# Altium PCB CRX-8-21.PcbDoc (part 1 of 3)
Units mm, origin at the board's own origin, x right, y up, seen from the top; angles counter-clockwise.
Board outline 160.02 x 101.6 mm, 2 copper layers (TopLayer, BottomLayer), stack 1.535 mm thick; 254 components, 127 nets, 595 pads, 4322 vias.
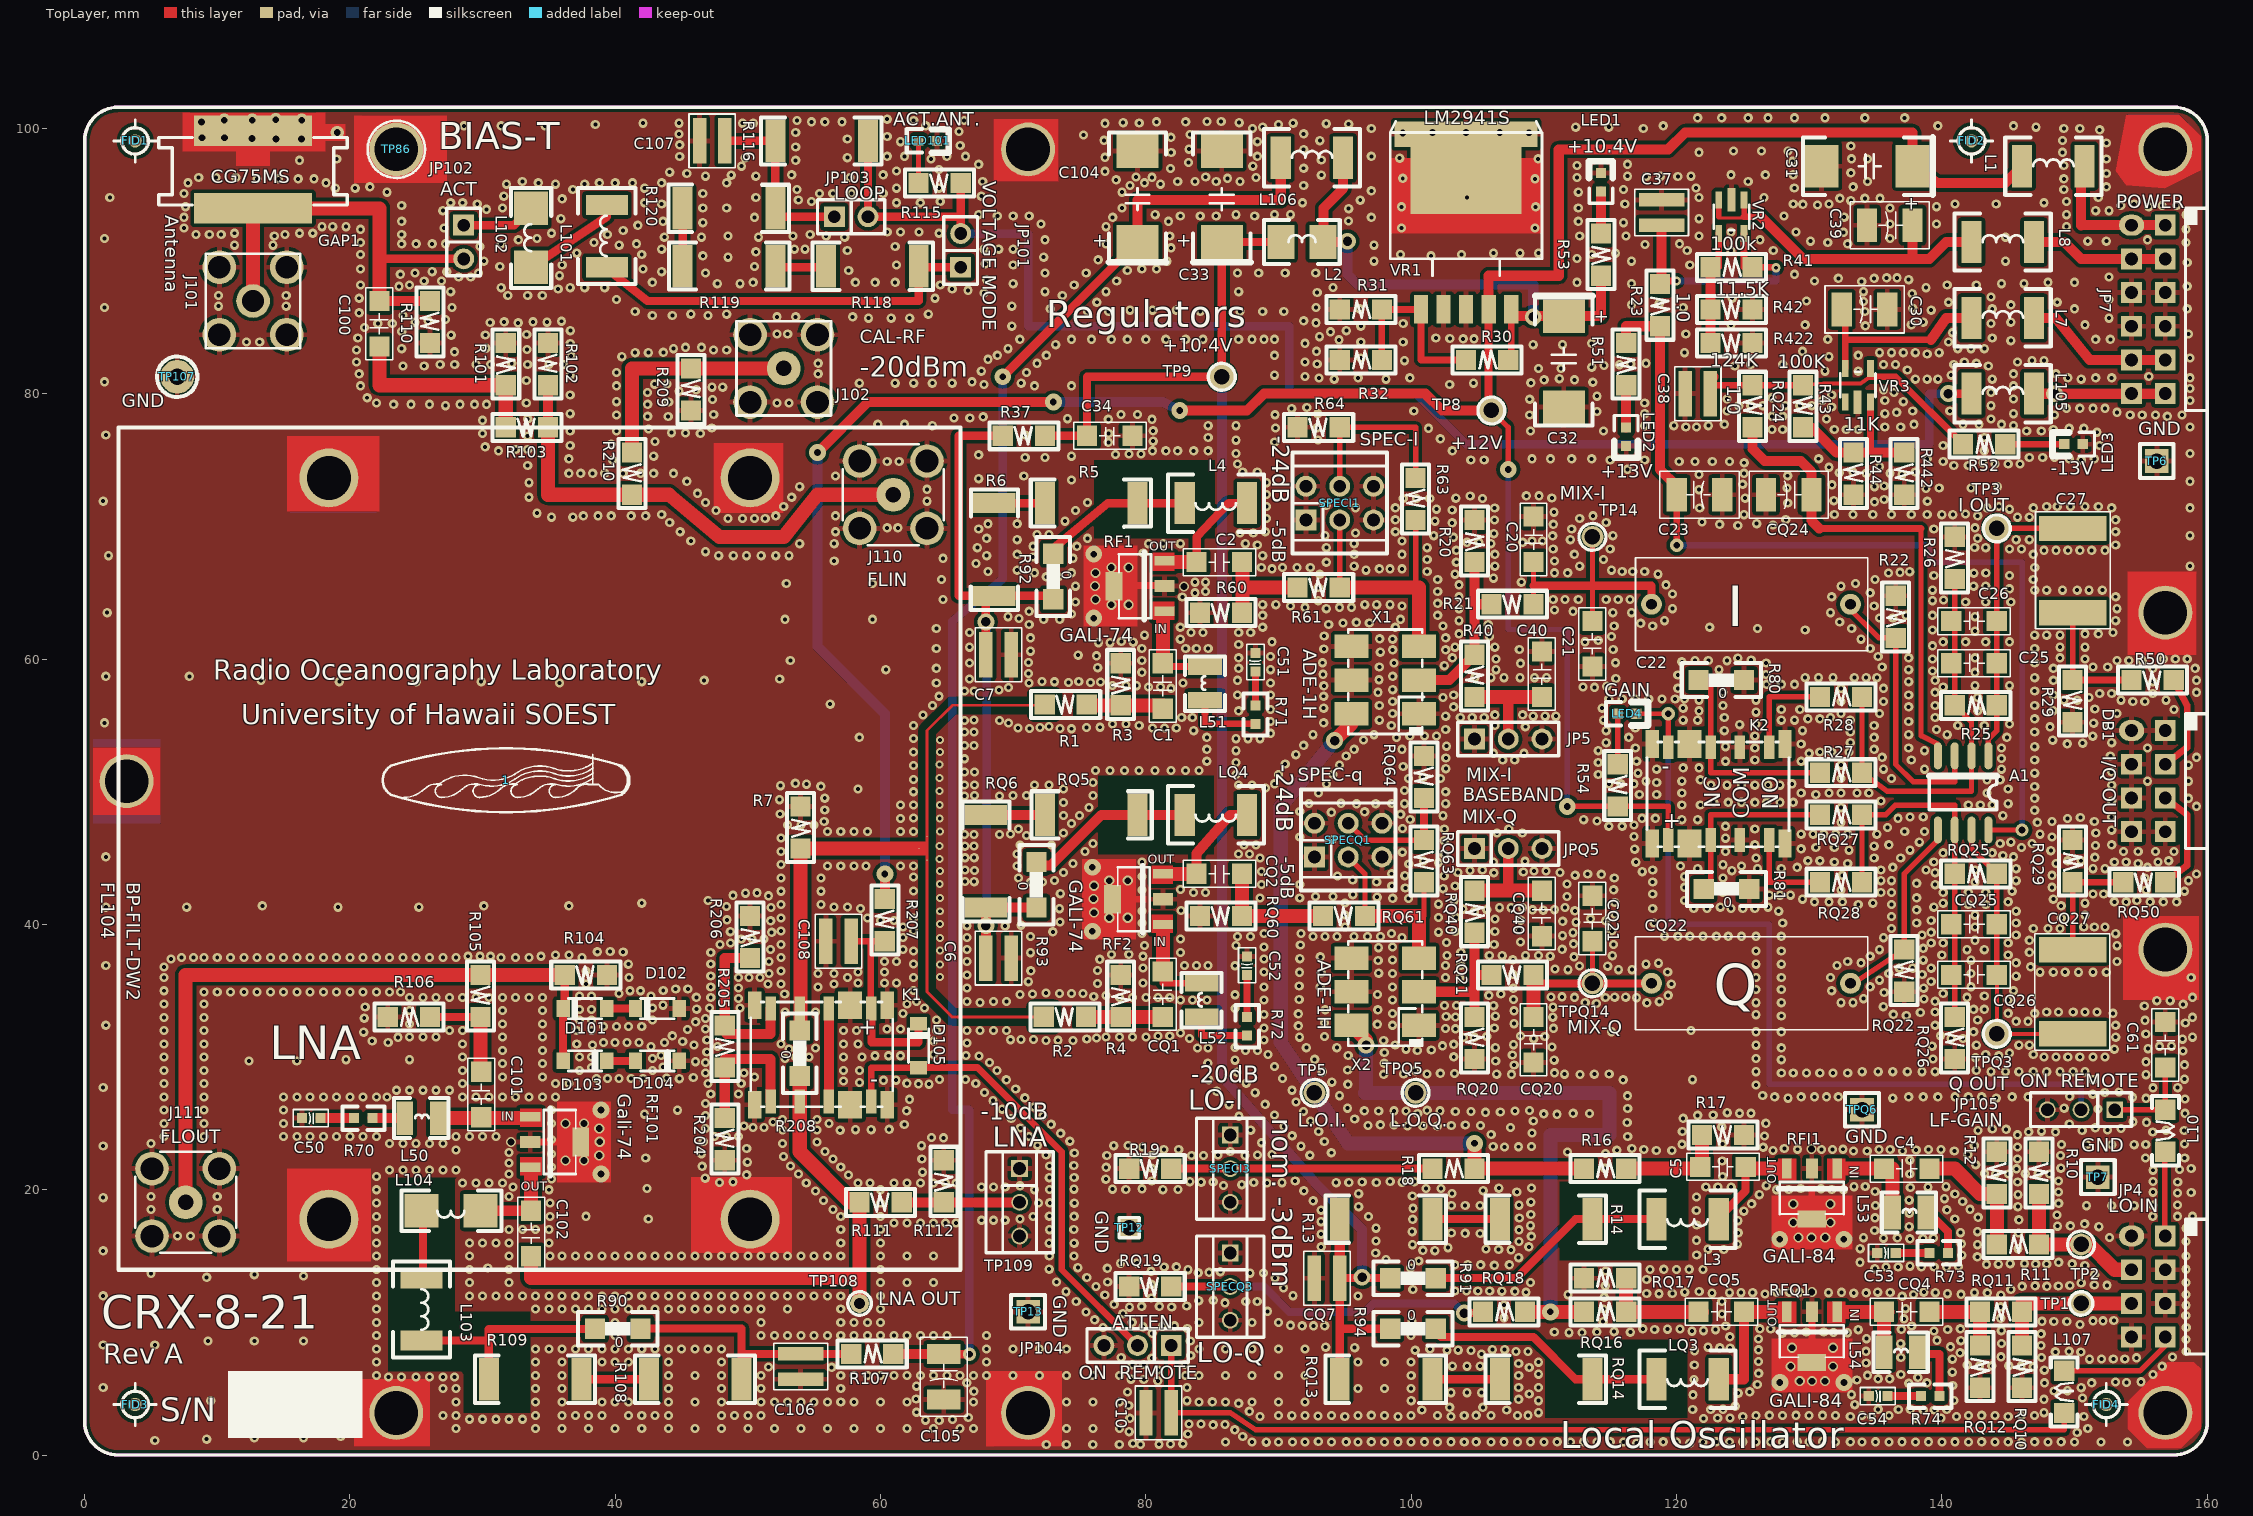
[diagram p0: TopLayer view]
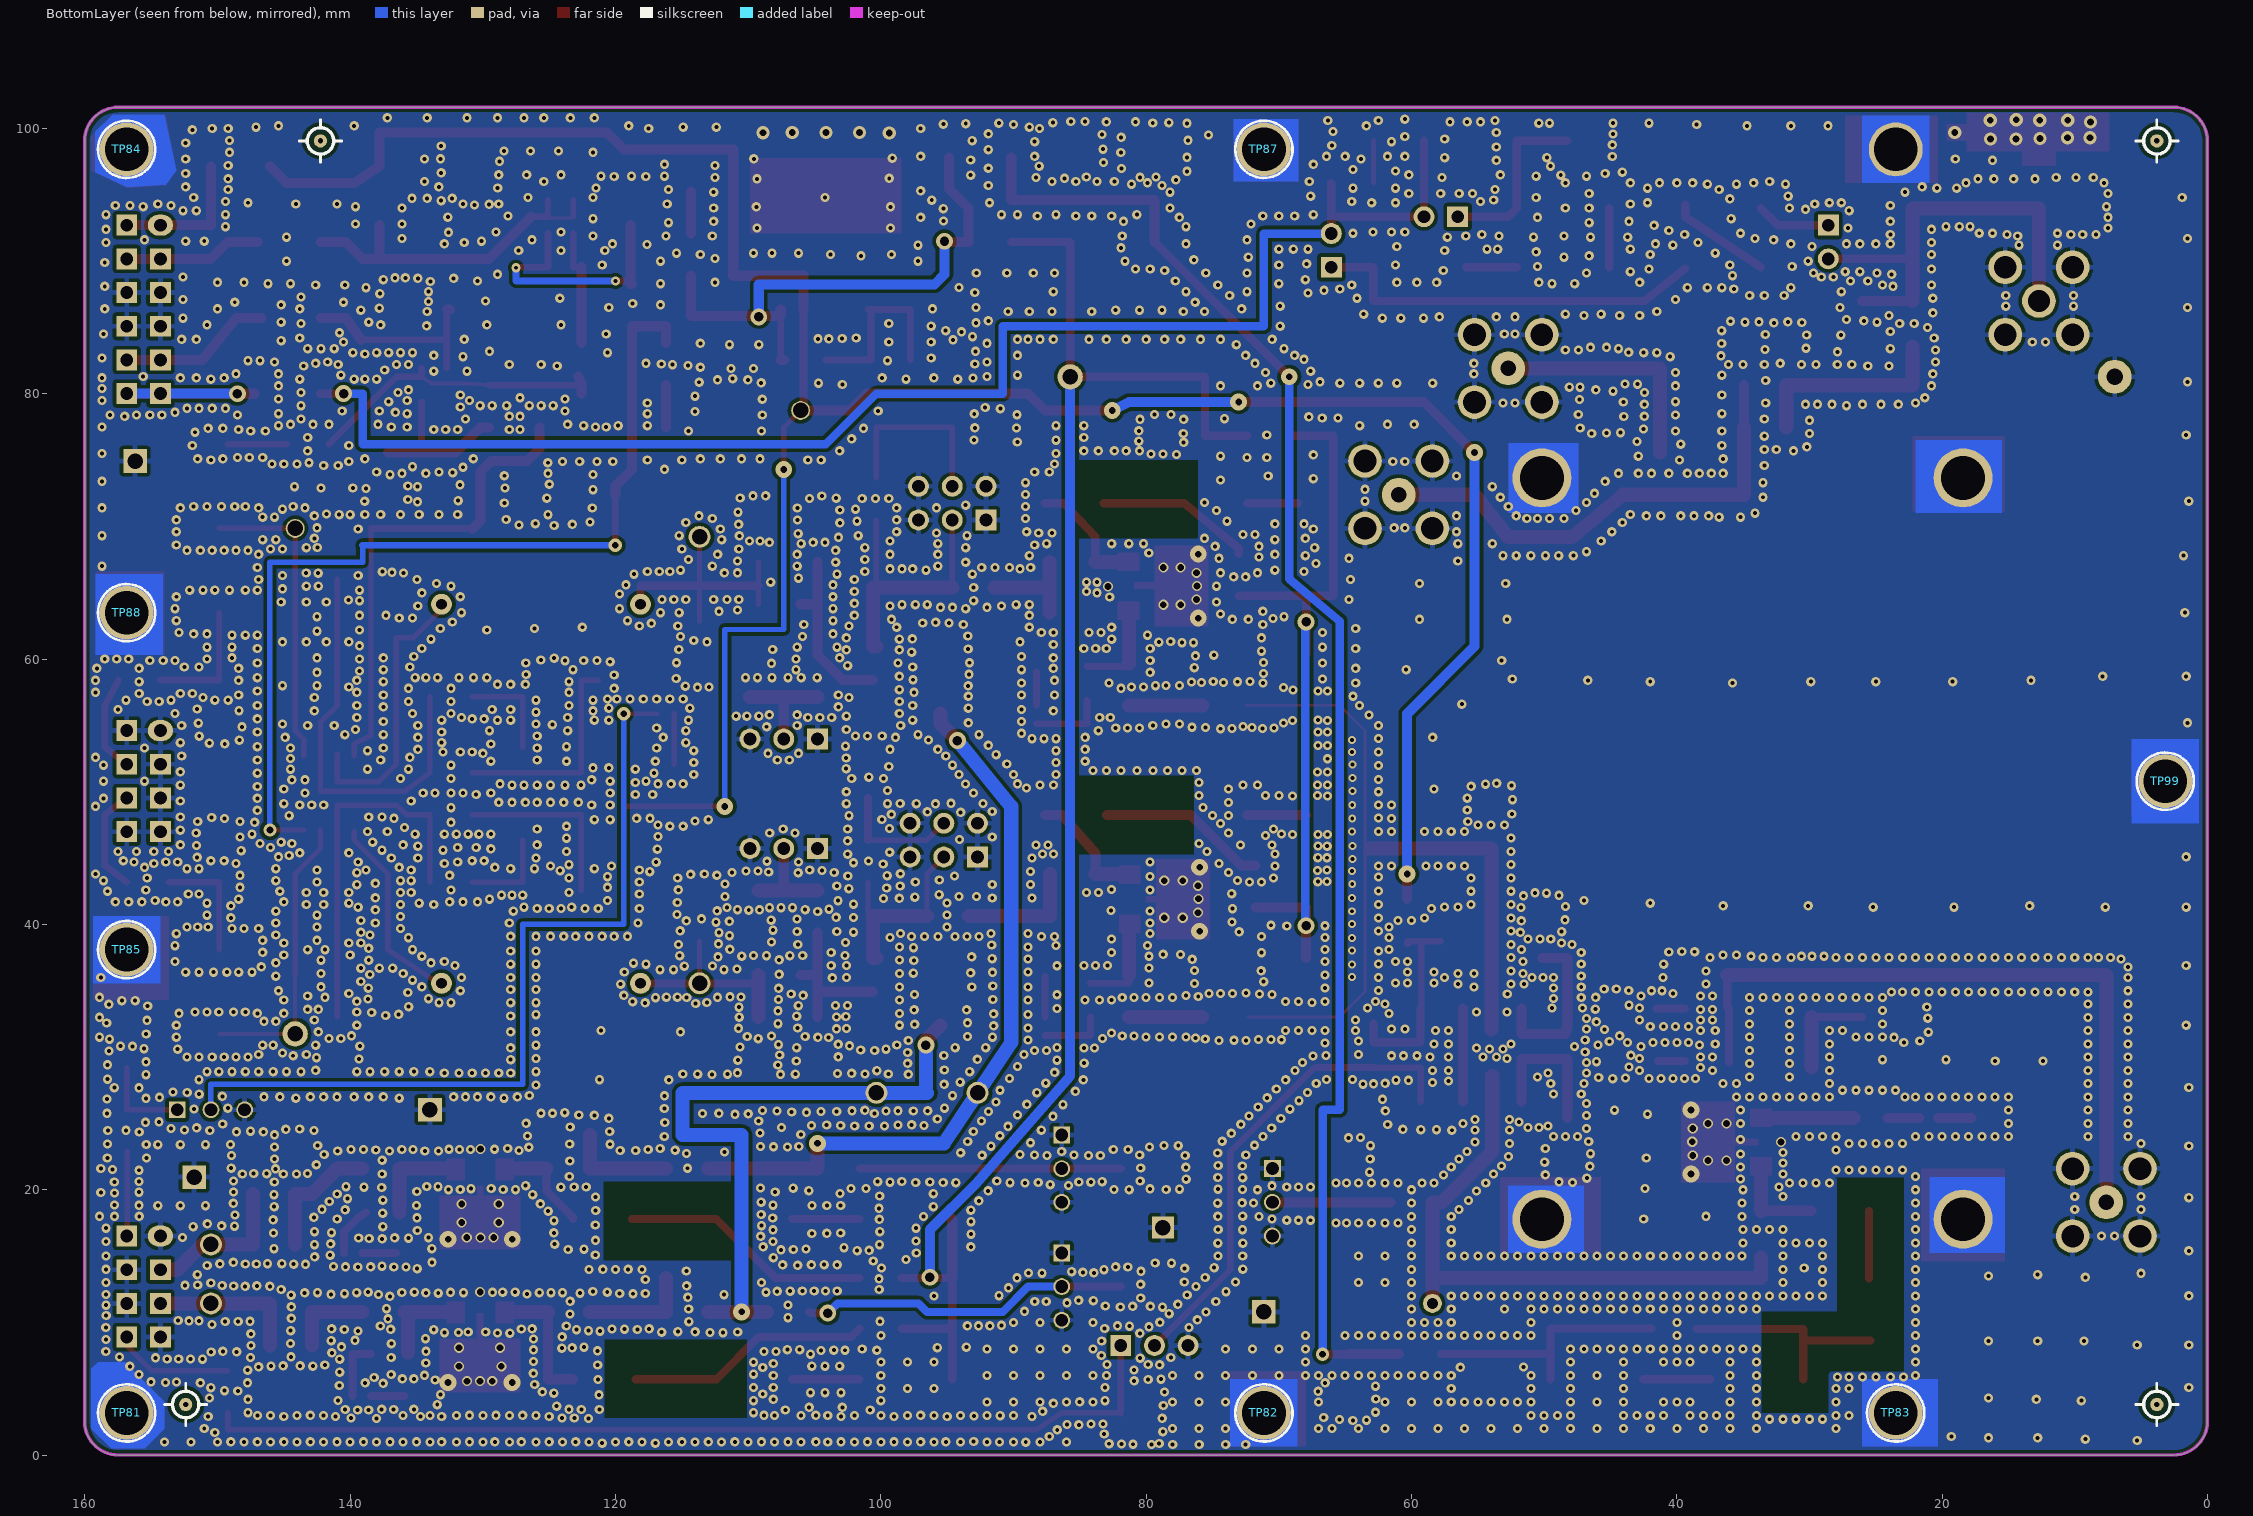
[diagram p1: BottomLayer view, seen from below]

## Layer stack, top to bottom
TopSolder: solder mask 0.02, Solder Resist, Dk 4
TopLayer: signal copper 0.035
Dielectric1: dielectric 1.465, FR-4, Dk 4.74
BottomLayer: signal copper 0.035
BottomSolder: solder mask 0.02, Solder Resist, Dk 4

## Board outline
0,2.54 0,99.06 cw(c2.54,99.06) 2.54,101.6 157.48,101.6 cw(c157.48,99.06) 160.02,99.06 160.02,2.54 cw(c157.48,2.54) 157.48,0 2.54,0 cw(c2.54,2.54)

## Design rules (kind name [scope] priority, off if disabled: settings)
Clearance Clearance_4 [InNet('RF') vs InPolygon] p1: gap=0.55 ignorepadtopadclearanceinfootprint=FALSE
Clearance Clearance_2 [InNet('RF') vs InPolygon] p2: gap=0.55 ignorepadtopadclearanceinfootprint=FALSE
Clearance Clearance_3 [InNet('RF') vs InPolygon] p3: gap=0.55 ignorepadtopadclearanceinfootprint=FALSE
Clearance Clearance_1 [InPolygon] p4: gap=0.257 ignorepadtopadclearanceinfootprint=FALSE
Clearance [InNet('rfi2x') vs InPolygon] p5: gap=0.55 ignorepadtopadclearanceinfootprint=FALSE
ComponentClearance [All] p1 off: gap=0.254 collisioncheckmode=3 verticalgap=0.254 showdistances=FALSE
FabricationTestPointUsage TestPointUsage [All] p1: valid=0 allowmultiple=FALSE
FabricationTestpoint Testpoint [All] p1: side=3 testpointundercomponent=TRUE minsize=1.016 maxsize=2.54 preferedsize=1.524 minholesize=0.508 maxholesize=1.016 preferedholesize=0.813 testpointgrid=0.025 allowsidetop=TRUE allowsidebottom=TRUE usegrid=TRUE gridtolerance=0
HoleSize [All] p1: absolutevalues=TRUE maxlimit=10 minlimit=0.025 maxpercent=80.000 minpercent=20.000
PlaneClearance PlaneClearance_15 [HasPad('TP88-TP')] p1 off: clearance=1.27
PlaneClearance PlaneClearance_16 [HasPad('TP85-TP')] p2 off: clearance=1.27
PlaneClearance PlaneClearance_13 [HasPad('TP86-TP')] p3 off: clearance=1.27
PlaneClearance PlaneClearance_14 [HasPad('TP84-TP')] p4 off: clearance=1.27
PlaneClearance PlaneClearance_17 [HasPad('TP81-TP')] p5 off: clearance=1.27
PlaneClearance PlaneClearance_20 [HasPad('TP99-TP')] p6 off: clearance=1.27
PlaneClearance PlaneClearance_21 [HasPad('TP83-TP')] p7 off: clearance=1.27
PlaneClearance PlaneClearance_18 [HasPad('TP87-TP')] p8 off: clearance=1.27
PlaneClearance PlaneClearance_19 [HasPad('TP82-TP')] p9 off: clearance=1.27
PlaneClearance PlaneClearance_4 [HasPad('TPQ3-TP')] p10 off: clearance=0.381
PlaneClearance PlaneClearance_5 [HasPad('TP8-TP')] p11 off: clearance=0.381
PlaneClearance PlaneClearance_6 [HasPad('TP14-TP')] p12 off: clearance=0.381
PlaneClearance PlaneClearance_1 [HasPad('TP3-TP')] p13 off: clearance=0.381
PlaneClearance PlaneClearance_2 [HasPad('TP2-TP')] p14 off: clearance=0.381
PlaneClearance PlaneClearance_3 [HasPad('TP1-TP')] p15 off: clearance=0.381
PlaneClearance PlaneClearance_10 [HasPad('TP5-TP')] p16 off: clearance=0.381
PlaneClearance PlaneClearance_11 [HasPad('TP12-TP')] p17 off: clearance=0.381
PlaneClearance PlaneClearance_12 [HasPad('TP108-TP')] p18 off: clearance=0.381
PlaneClearance PlaneClearance_7 [HasPad('TPQ14-TP')] p19 off: clearance=0.381
PlaneClearance PlaneClearance_8 [HasPad('TP9-TP')] p20 off: clearance=0.381
PlaneClearance PlaneClearance_9 [HasPad('TPQ5-TP')] p21 off: clearance=0.381
PlaneClearance [All] p22 off: clearance=0.254
PlaneConnect PlaneConnect_1 [All] p1 off: planeconnectstyle=Relief reliefexpansion=0.508 reliefentries=4 reliefconductorwidth=0.254 reliefairgap=0.254
PlaneConnect [All] p2 off: planeconnectstyle=Relief reliefexpansion=0.508 reliefentries=4 reliefconductorwidth=0.254 reliefairgap=0.254
PolygonConnect PolygonConnect_1 [IsVia] p1 off: connectstyle=Direct reliefconductorwidth=0.254 reliefentries=4 polygonreliefangle="90 Angle" airgapwidth=0.254
PolygonConnect PolygonConnect_2 [All] p2: thpad.connectstyle=Relief thpad.reliefconductorwidth=0.4 thpad.reliefentries=4 thpad.polygonreliefangle="90 Angle" thpad.airgapwidth=0.257 smdpad.connectstyle=Relief smdpad.reliefconductorwidth=0.4 smdpad.reliefentries=4 smdpad.polygonreliefangle="90 Angle" smdpad.airgapwidth=0.257 via.connectstyle=Direct via.reliefconductorwidth=0.254 via.reliefentries=4 via.polygonreliefangle="90 Angle" via.airgapwidth=0.254
PolygonConnect [All] p3 off: connectstyle=Relief reliefconductorwidth=0.254 reliefentries=4 polygonreliefangle="90 Angle" airgapwidth=0.257
RoutingPriority [All] p1: routingpriority=2
RoutingVias [All] p1: holewidth=0.3 width=0.7 viastyle="Through Hole" minholewidth=0.3 minwidth=0.7 maxholewidth=1.1 maxwidth=2
SilkToSilkClearance [All] p1 off: silktosilkclearance=0.254
SilkToSolderMaskClearance [IsPad] p1 off: minsilkscreentomaskgap=0.254 clearancetoexposedcopper=TRUE
SolderMaskExpansion [All] p1: expansion=0.051
UnpouredPolygon [All] p1 off:
Width [All] p1: maxlimit=10 minlimit=0.2 preferedwidth=0.635 bottomlayer_minwidth=0.254 minimp=50.000000 maximp=50.000000 favimp=50.000000
20 further rules are at their usual default settings.

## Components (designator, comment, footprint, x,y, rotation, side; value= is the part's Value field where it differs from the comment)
1 "" LOGOTINY 31.773,50.867 r0 top
A1 "OPA2227UA" SO-8 143.51,52.705 r270 top
C1 "22nF" C1206 81.28,59.69 r270 top
C2 "22nF" C1206 83.82,67.31 r0 top
C4 "22nF" C1206 139.065,21.59 r180 top
C5 "470nF" C1206 121.793,21.717 r0 top
C6 "470nF" C0612 67.945,37.465 r0 top
C7 "470nF" C0612 67.945,60.325 r0 top
C10 "470nF" C0612 81.915,3.175 r180 top
C20 "1nF" C1206 109.22,67.31 r90 top
C21 "100nF  NPO" C1206 113.665,62.865 r270 top
C22 "470nF" BFC2_416#1 118.11,64.135 r0 top
C23 "4.7uF" C1210 120.015,72.39 r0 top
C25 "1800pF NPO" C1206 144.145,59.69 r180 top
C26 "3650" C1206 144.145,62.865 r180 top
C27 "22uF 25V NP" 2220 149.86,69.85 r270 top
C30 "4.7uF" C1210 135.89,86.36 r180 top
C31 "22uF 20V" C2917 137.795,97.155 r180 top
C32 "22uF 20V" C2917 111.506,85.852 r270 top
C33 "22uF 20V" C2917 85.725,91.44 r90 top
C34 "470nF" C1206 75.565,76.835 r0 top
C37 "470nF" C0612 118.872,92.71 r90 top
C38 "470nF" C0612 122.555,80.01 r180 top
C39 "4.7uF" C1210 137.795,92.71 r180 top
C40 "1nF" C1206 109.855,57.15 r90 top
C50 "330pF" C0603 17.78,25.4 r180 top
C51 "330pF" C0603 88.265,59.055 r90 top
C52 "330pF" C0603 87.63,36.195 r90 top
C53 "330pF" C0603 136.525,15.24 r180 top
C54 "330pF" C0603 135.89,4.445 r180 top
C61 "22nF" C1206 156.845,29.21 r90 top
C100 "22nF" C1206 22.225,86.995 r270 top
C101 "10nF" C1206 29.9,28.9 r270 top
C102 "47nF" C1206 33.655,18.415 r270 top
C104 "22uF 20V" C2917 79.375,91.44 r90 top
C105 "4.7uF" C1210 64.77,7.62 r270 top
C106 "470nF" C0612 53.975,7.62 r270 top
C107 "470nF" C0612 48.26,99.06 r180 top
C108 "470nF" C0612 57.785,38.735 r180 top
CQ1 "22nF" C1206 81.28,36.449 r270 top
CQ2 "22nF" C1206 83.82,43.815 r0 top
CQ4 "22nF" C1206 139.065,10.795 r180 top
CQ5 "470nF" C1206 125.095,10.795 r180 top
CQ7 "470nF" C0612 94.615,13.335 r180 top
CQ20 "1nF" C1206 109.22,33.02 r270 top
CQ21 "100nF  NPO" C1206 113.665,38.735 r90 top
CQ22 "470nF" BFC2_416#2 118.11,35.56 r0 top
CQ24 "4.7uF" C1210 130.175,72.39 r180 top
CQ25 "1800pF NPO" C1206 144.145,40.005 r180 top
CQ26 "FSV" C1206 144.145,36.195 r180 top
CQ27 "22uF 25V NP" 2220 149.86,31.75 r90 top
CQ40 "1nF" C1206 109.855,42.545 r270 top
D101 "1N4148W" SOD123 37.719,33.655 r180 top
D102 "1N4148W" SOD123 43.18,33.655 r180 top
D103 "1N4148W" SOD123 37.719,29.718 r0 top
D104 "1N4148W" SOD123 43.18,29.718 r0 top
D105 "1N4148W" SOD123 62.865,30.861 r90 top
DB1 "I/Q OUT" TSW-4X2M 154.305,54.61 r90 top locked
FID1 "" FIDUCIAL2 3.81,99.06 r0 top
FID2 "" FIDUCIAL2 142.24,99.06 r0 top
FID3 "" FIDUCIAL2 3.81,3.81 r0 top
FID4 "" FIDUCIAL2 152.4,3.81 r0 top
FL104 "BP-FILT-DW2" BP-FILT-DW2 34.29,45.72 r90 top locked
GAP1 "CG75MS" SG-1 12.7,93.98 r90 top
J101 "Antenna" MCX_SMA#1 12.7,86.995 r0 top
J102 "CAL-RF" MCX_SMA#2 52.705,81.915 r0 top
J110 "FLIN" MCX_SMA#2 60.96,72.39 r0 top
J111 "FLOUT" MCX_SMA#2 7.62,19.05 r0 top
JP4 "LO IN" TSW-4X2M 154.305,16.51 r90 top locked
JP5 "MIX-I" SIP3#1 104.775,53.975 r0 top
JP7 "POWER" TSW-6X2M 154.305,92.71 r90 top locked
JP101 "VOLTAGE MODE" SIP2 66.04,89.535 r90 top
JP102 "ACT" SIP2 28.575,92.71 r270 top
JP103 "LOOP" SIP2 56.515,93.345 r0 top
JP104 "ATTEN" SIP3#1 81.915,8.255 r180 top
JP105 "LF-GAIN" SIP3#2 153.035,26.035 r180 top
JPQ5 "MIX-Q" SIP3#1 104.775,45.72 r0 top
K1 "G6K-2F-RF-S DC12" RELAY-RF 59.309,33.655 r180 top
K2 "G6K-2F-RF-S DC12" RELAY-RF 119.38,46.355 r0 top
L1 "Ferrite" L1812 146.05,97.155 r0 top
L2 "2.2uH" L1210#1 90.17,91.44 r0 top
L3 "4.7uH" L1812 123.19,17.78 r180 top
L4 "4.7uH" L1812 87.63,71.755 r180 top
L7 "Ferrite" L1812 142.24,85.725 r0 top
L8 "Ferrite" L1812 142.24,91.44 r0 top
L10 "Ferrite" L1206 156.845,22.86 r90 top
L50 "620nH" L1008 24.13,25.4 r0 top
L51 "620nH" L1008 84.455,56.896 r90 top
L52 "620nH" L1008 84.201,33.02 r90 top
L53 "620nH" L1008 136.271,18.288 r0 top
L54 "620nH" L1008 135.636,7.747 r0 top
L101 "4.7uH" L1812 39.37,89.535 r90 top
L102 "0.47uH" L1210#2 33.655,89.535 r90 top
L103 "4.7uH" L1812 25.4,13.335 r270 top
L104 "0.47uH" L1210#2 29.845,18.415 r180 top
L105 "Ferrite" L1812 142.24,80.01 r0 top
L106 "Ferrite" L1812 90.17,97.79 r0 top
L107 "Ferrite" L1206 149.225,6.35 r270 top
LED1 "+10.4V" LED0603 114.3,95.25 r90 top
LED2 "+13V" LED0603 116.205,77.47 r270 top
LED3 "-13V" LED0603 150.622,76.2 r180 top
LED4 "GAIN" LED0603 115.57,55.88 r0 top
LED101 "ACT.ANT." LED0603 62.865,99.06 r0 top
LQ3 "4.7uH" L1812 123.19,5.715 r180 top
LQ4 "4.7uH" L1812 87.63,48.26 r180 top
R1 "75" R1206 72.371,56.588 r0 top
R2 "75" R1206 72.308,33.033 r0 top
R3 "49.9" R1206 78.105,56.515 r90 top
R4 "49.9" R1206 78.105,33.02 r90 top
R5 "27R4 1W" R2512 72.39,71.755 r0 top
R6 "27R4 1W" R2512 68.58,64.77 r90 top
R7 "499" R1206 53.975,45.72 r90 top
R10 "442" R1206 147.32,22.86 r270 top
R11 "11.8" R1206 147.32,15.875 r180 top
R12 "442" R1206 144.145,22.86 r270 top
R13 "20R5 1W" R2512 94.615,17.78 r0 top
R14 "20R5 1W" R2512 106.68,17.78 r0 top
R16 "5.76" R1206 116.205,21.59 r180 top
R17 "866" R1206 121.92,24.13 r0 top
R18 "806" R1206 104.775,21.59 r180 top
R19 "54.9" R1206 78.74,21.59 r0 top
R20 "249" R1206 104.775,67.31 r90 top
R21 "620" R1206 106.045,64.135 r0 top
R22 "4.99k" R1206 136.525,61.595 r90 top
R23 "1.0" R1206 118.745,85.09 r90 top
R25 "33.2k" R1206 144.145,56.515 r180 top
R26 "3650" R1206 140.97,66.04 r90 top
R27 "1100" R1206 133.985,51.435 r180 top
R28 "13K" R1206 133.985,57.15 r180 top
R29 "10K" R1206 149.86,58.42 r270 top
R30 "1.8K" R1206 107.315,82.55 r180 top
R31 "249" R1206 97.79,86.36 r180 top
R32 "FSV" R1206 97.79,82.55 r180 top
R37 "2.74" R1206 69.215,76.835 r0 top
R40 "1k" R1206 104.775,60.325 r270 top
R41 "100k" R1206 125.73,89.535 r180 top
R42 "11.5K" R1206 122.555,86.36 r0 top
R43 "100K" R1206 129.54,80.645 r270 top
R44 "11K" R1206 133.35,75.565 r270 top
R50 "22.1" R1206 154.305,58.42 r0 top
R51 "10K" R1206 116.205,80.645 r90 top
R52 "10K" R1206 144.78,76.2 r180 top
R53 "10K" R1206 114.3,88.9 r90 top
R54 "10K" R1206 115.57,52.07 r270 top
R60 "442" R1206 84.074,63.5 r0 top
R61 "11.8" R1206 91.44,65.405 r0 top
R63 "383" R1206 100.33,73.66 r270 top
R64 "54.9" R1206 91.44,77.47 r0 top
R70 "150" R0603 20.32,25.4 r0 top
R71 "150" R0603 88.265,56.515 r270 top
R72 "150" R0603 87.63,33.02 r270 top
R73 "150" R0603 139.065,15.24 r0 top
R74 "150" R0603 138.43,4.445 r0 top
R80 "ZERO" ZEROHM 125.095,58.42 r180 top
R81 "ZERO" ZEROHM 125.476,42.672 r180 top
R90 "ZERO" ZEROHM 41.91,9.525 r180 top
R91 "ZERO" ZEROHM 98.425,13.335 r0 top
R92 "ZERO" ZEROHM 73.025,67.945 r270 top
R93 "ZERO" ZEROHM 71.755,41.275 r90 top
R94 "ZERO" ZEROHM 98.425,9.525 r0 top
R101 "866" R1206 31.75,80.645 r90 top
R102 "866" R1206 34.925,83.82 r270 top
R103 "5.76" R1206 31.75,77.47 r0 top
R104 "866" R1206 36.195,36.195 r0 top
R105 "5.76" R1206 29.845,36.195 r270 top
R106 "866" R1206 26.035,33.02 r180 top
R107 "5.76" R1206 60.96,7.62 r180 top
R108 "27R4 1W" R2512 42.545,5.715 r0 top
R109 "27R4 1W" R2512 30.48,5.715 r0 top
R110 "100k" R1206 26.035,86.995 r270 top
R111 "107" R1206 58.42,19.05 r0 top
R112 "4.99K" R1206 64.77,19.05 r90 top
R115 "10K" R1206 62.865,95.885 r0 top
R116 "45ohm 2W" R2512 52.07,99.06 r0 top
R118 "15ohm 3W" R2512 62.88,89.611 r180 top
R119 "15ohm 3W" R2512 52.067,89.626 r180 top
R120 "15ohm 3W" R2512 45.085,93.98 r0 top
R204 "95.3" R1206 48.26,25.4 r270 top
R205 "71.5" R1206 48.26,29.21 r90 top
R206 "95.3" R1206 50.165,37.465 r90 top
R207 "5.76" R1206 60.325,41.91 r270 top
R208 "ZERO" ZEROHM 53.909,28.575 r90 top
R209 "57.6" R1206 45.72,81.915 r270 top
R210 "365" R1206 41.275,75.565 r270 top
R422 "124K" R1206 122.555,83.82 r0 top
R442 "124K" R1206 137.16,75.565 r270 top
RF1 "GALI-74" GALI-74 81.4,65.5 r90 top
RF2 "GALI-74" GALI-74 81.3,41.9 r90 top
RF101 "Gali-74" GALI-74 33.59,23.6 r270 top
RFI1 "GALI-84" GALI-74 130.2,21.6 r180 top
RFQ1 "GALI-84" GALI-74 130.205,10.8 r180 top
RQ5 "27R4 1W" R2512 79.375,48.26 r180 top
RQ6 "27R4 1W" R2512 67.945,41.275 r90 top
RQ10 "442" R1206 146.05,5.08 r90 top
RQ11 "11.8" R1206 146.05,10.795 r180 top
RQ12 "442" R1206 142.875,5.08 r90 top
RQ13 "20R5 1W" R2512 94.615,5.715 r0 top
RQ14 "20R5 1W" R2512 106.68,5.715 r0 top
RQ16 "5.76" R1206 116.205,10.795 r180 top
RQ17 "866" R1206 116.205,13.335 r180 top
RQ18 "806" R1206 108.585,10.795 r180 top
RQ19 "54.9" R1206 78.74,12.7 r0 top
RQ20 "249" R1206 104.775,33.02 r270 top
RQ21 "620" R1206 106.045,36.195 r0 top
RQ22 "4.99k" R1206 137.16,38.1 r270 top
RQ24 "1.0" R1206 125.73,80.645 r270 top
RQ25 "33.2k" R1206 144.145,43.815 r180 top
RQ26 "3650" R1206 140.97,33.02 r270 top
RQ27 "1100" R1206 133.985,48.26 r180 top
RQ28 "13K" R1206 133.985,43.18 r180 top
RQ29 "10K" R1206 149.86,43.18 r90 top
RQ40 "1k" R1206 104.775,39.37 r90 top
RQ50 "22.1" R1206 153.67,43.18 r0 top
RQ60 "442" R1206 84.074,40.64 r0 top
RQ61 "11.8" R1206 93.345,40.64 r0 top
RQ63 "383" R1206 100.965,46.355 r270 top
RQ64 "54.9" R1206 100.965,52.705 r270 top
SPECI1 "SPEC-I" TEST-6 92.075,70.485 r0 top locked
SPECI3 "LO-I" TEST-JUMP 86.36,24.13 r270 top
SPECQ1 "SPEC-q" TEST-6 92.71,45.085 r0 top locked
SPECQ3 "LO-Q" TEST-JUMP 86.36,15.24 r270 top
TP1 "LO Q IN" TP_TIP#1 150.495,11.43 r0 top
TP2 "LO I IN" TP_TIP#2 150.495,15.875 r0 top
TP3 "I OUT" TP_TIP#3 144.145,69.85 r0 top
TP5 "L.O.I." TP_TIP#2 92.71,27.305 r0 top
TP6 "GND" TP#1 156.21,74.93 r0 top
TP7 "GND" TP#1 151.765,20.955 r0 top
TP8 "+12V" TP_TIP#3 106.045,78.74 r0 top
TP9 "+10.4V" TP_TIP#4 85.725,81.28 r0 top
TP12 "GND" TP_SMALL 78.74,17.145 r0 top
TP13 "GND" TP#1 71.12,10.795 r0 top
TP14 "MIX-I" TP_TIP#2 113.665,69.215 r0 top
TP81 "GND" MOUNT-3 156.845,3.175 r0 bottom locked
TP82 "GND" MOUNT-3 71.12,3.175 r0 bottom locked
TP83 "GND" MOUNT-3 23.495,3.175 r0 bottom locked
TP84 "GND" MOUNT-3 156.845,98.425 r0 bottom locked
TP85 "GND" MOUNT-3 156.845,38.1 r0 bottom locked
TP86 "GND" MOUNT-3 23.495,98.425 r0 top locked
TP87 "GND" MOUNT-3 71.12,98.425 r0 bottom locked
TP88 "GND" MOUNT-3 156.845,63.5 r0 bottom locked
TP99 "GND" MOUNT-3 3.175,50.8 r0 bottom locked
TP107 "GND" TP_BIG 6.985,81.28 r0 top
TP108 "LNA OUT" TP_TIP#5 58.42,11.43 r0 top
TP109 "LNA" TEST-JUMP 70.485,21.59 r270 top
TPQ3 "Q OUT" TP_TIP#6 144.145,31.75 r0 top
TPQ5 "L.O.Q." TP_TIP#2 100.33,27.305 r0 top
TPQ6 "GND" TP#2 133.985,26.035 r0 top
TPQ14 "MIX-Q" TP_TIP#1 113.665,35.56 r0 top
VR1 "LM2941S" TO-263-5 104.14,86.36 r0 top
VR2 "MIC5235YM5" SOT-23-5 125.095,94.615 r0 top
VR3 "MIC5270YM5" SOT-23-5 132.715,79.375 r180 top
X1 "ADE-1H" CD542 97.79,58.42 r90 top
X2 "ADE-1H" CD542 97.79,34.925 r90 top
? "Comment" RF 63.496,45.727 r0 top

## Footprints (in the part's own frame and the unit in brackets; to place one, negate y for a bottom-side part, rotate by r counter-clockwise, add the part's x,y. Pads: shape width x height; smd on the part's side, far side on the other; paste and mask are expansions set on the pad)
2220 [mm]
  rect 1.905x5.08 smd: 1(0,0) 2(6.35,0)
  silkscreen extent -1.25,-2.8 7.55,2.85
BFC2_416#1 [mil]
  round 62 hole 32 mask+5: 1(0,0) 2(590.55,0)
  silkscreen extent -47,-138 642,138
BFC2_416#2 [mil]
  round 62 hole 32: 1(0,0) 2(590.55,0)
  silkscreen extent -47,-138 642,138
BP-FILT-DW2 [mm]
  round 4.445 hole 3.3: 5(-27.94,15.875) 6(-27.94,-15.875) 7(27.94,15.875) 8(27.94,-15.875)
  silkscreen extent -31.75,-31.75 31.75,31.75
C0603 [mil]
  rect 30x30 smd: 1(0,0) 2(55,0)
  silkscreen extent -24,-26 81,26
C0612 [mil]
  rect 40x135 smd: 1(0,0) 2(75,0)
  silkscreen extent -31,-80 106,80
C1206 [mil]
  rect 60x60 smd: 1(0,0) 2(135,0)
  silkscreen extent -40,-40 175,40
C1210 [mil]
  rect 60x100 smd: 1(0,0) 2(135,0)
  silkscreen extent -50,-70 185,70
C2917 [mil]
  rect 100x125 smd: 1(0,0) 2(270,0)
  silkscreen extent -60,-85 325,85
CD542 [mil]
  rect 70x100 smd: 1(-100,-110) 2(0,-110) 3(100,-110) 4(100,90) 5(0,90) 6(-100,90)
  silkscreen extent -160,-120 150,100
FIDUCIAL2 [mm]
  round 2 on Top Solder: 0(0,0)
  round 2 on Bottom Solder: 0_1(0,0)
  round 1 hole 0.406: 0_2(0,0)
  TopLayer circle w0.25: c0,0 r1
  BottomLayer circle w0.25: c0,0 r1
  silkscreen extent -1.6,-1.6 1.6,1.6
GALI-74 [mil]
  rect 28x60 smd: 1(-75,0) 3(75,0)
  rect 36x60 smd: 2(0,0)
  rect 85x50 smd: 4(0,150)
  TopLayer region: -119.99,240 -119.99,80 120.01,80 120.01,240
  TopLayer region: 45.01,35 45.01,-30 100.01,-30 100.01,35
  TopLayer region: -99.99,35 -99.99,-30 -44.99,-30 -44.99,35
  TopLayer region: -7.87,84.68 -7.87,19.68 12.13,19.68 12.13,84.68
  silkscreen extent -100,40 100,135
L1008 [mm]
  rect 1.27x2.54 smd: 1(0,0) 2(2.54,0)
  silkscreen extent -0.8,-1.5 3.3,1.5
L1206 [mil]
  rect 60x60 smd: 1(0,0) 2(125,0)
  silkscreen extent -40,-40 165,40
L1210#1 [mil]
  rect 80x100 smd: 1(0,0) 2(125,0)
  silkscreen extent -50,-65 175,65
L1210#2 [mil]
  rect 100x100 smd mask+3: 1(0,0) 2(175,0)
  silkscreen extent -62,-60 235,60
L1812 [mil]
  rect 60x125 smd: 1(0,0) 2(185,0)
  silkscreen extent -50,-85 235,85
LED0603 [mil]
  rect 30x30 smd: 1(0,0) 2(55,0)
  silkscreen extent -35,-35 90,35
LOGOTINY [mm]
  silkscreen extent -9.29,-2.41 9.29,2.41
MCX_SMA#1 [mil]
  round 100 hole 65: 1(0,0)
  round 100 hole 67: 2(-100,100) 3(100,100) 4(-100,-100) 5(100,-100)
  silkscreen extent -140,-140 140,140
MCX_SMA#2 [mil]
  round 100 hole 46.06: 1(0,0)
  round 100 hole 67: 2(-100,100) 3(100,100) 4(-100,-100) 5(100,-100)
  silkscreen extent -140,-140 140,140
MOUNT-3 [mil]
  round 160 hole 129.92 mask+5: TP(0,0)
  silkscreen extent -85,-85 85,85
R0603 [mil]
  rect 30x30 smd: 1(0,0) 2(55,0)
  silkscreen extent -35,-35 90,35
R1206 [mil]
  rect 60x60 smd: 1(0,0) 2(125,0)
  silkscreen extent -40,-40 165,40
R2512 [mm]
  rect 1.5x3.2 smd: 1(0,0) 2(6.985,0)
  silkscreen extent -1.07,-1.78 8,1.78
RELAY-RF [mm]
  rect 0.8x1.8 smd: 1(0,0) 2(3.2,0) 3(5.4,0) 4(7.6,0) 5(7.6,7) 6(5.4,7) 7(3.2,7) 8(0,7)
  rect 1x2.1 smd: 10(-1.2,-0.25) 12(8.8,-0.25) 13(8.8,7.25) 15(-1.2,7.25)
  rect 1.8x2.1 smd: 11(1.6,-0.25) 14(1.6,7.25)
  silkscreen extent -1.6,-0.5 9.1,7.4
RF [mm]
  round 0.1 smd mask-0.05: 1(-0.6,0) 2(0,0.9) 3(0,-0.9)
  TopLayer region: -0.1,-1 0.1,-1 0.1,1 -0.1,1
  TopLayer region: -1,-0.532 0,-0.532 0,0.532 -1,0.532
SG-1 [mil]
  rect 90x350 smd: 1(0,0) 2(230.32,0)
  silkscreen extent 10,-280 210,280
SIP2 [mil]
  rect 62x62 hole 38: 1(0,0)
  round 62 hole 38: 2(100,0)
  silkscreen extent -50,-50 150,50
SIP3#1 [mil]
  rect 62x62 hole 38: 1(0,0)
  round 62 hole 38: 2(100,0) 3(200,0)
  silkscreen extent -50,-50 250,50
SIP3#2 [mil]
  rect 50x50 hole 38: 1(0,0)
  round 50 hole 38: 2(100,0) 3(200,0)
  silkscreen extent -50,-50 250,50
SO-8 [mil]
  oval 80x24 smd: 1(0,0) 2(0,-50) 3(0,-100) 4(0,-150) 5(220,-150) 6(220,-100) 7(220,-50) 8(220,0)
  silkscreen extent 60,-175 160,25
SOD123 [mil]
  rect 40x50 smd: ANOD(-65,0) CATH(65,0)
  silkscreen extent -50,-30 50,30
SOT-23-5 [mil]
  rect 20x50 smd mask+5: 1(0,0) 3(-75,0) 4(-75,-100) 5(0,-100)
  rect 24x70 smd mask+5: 2(-37,0)
  silkscreen extent -90,-90 15,-15
TEST-6 [mil]
  rect 62x62 hole 38: 1(0,0)
  round 62 hole 38: 2(0,100) 3(100,0) 4(100,100) 5(200,0) 6(200,100)
  silkscreen extent -40,-100 240,200
TEST-JUMP [mil]
  rect 50x50 hole 38: 1(0,0)
  round 50 hole 38: 2(100,0) 3(200,0)
  silkscreen extent -50,-100 250,100
TO-263-5 [mil]
  rect 42x85 smd: 1(-134,0) 2(-67,0) 3(0,0) 4(67,0) 5(134,0)
  rect 425x75 smd: 6(0,520)
  rect 330x275 smd: 6_1(0,420)
  silkscreen extent -225,100 225,558
TP#1 [mil]
  rect 70x70 hole 46 mask+5: TP(0,0)
  silkscreen extent -50,-50 50,50
TP#2 [mil]
  rect 70x70 hole 46: TP(0,0)
  silkscreen extent -50,-50 50,50
TP_BIG [mil]
  round 100 hole 48: TP(0,0)
  silkscreen extent -60,-60 60,60
TP_SMALL [mil]
  rect 65x65 hole 46 mask+5: TP(0,0)
  silkscreen extent -30,-30 30,30
TP_TIP#1 [mil]
  round 65 hole 46 mask+3: TP(0,0)
  silkscreen extent -35,-35 35,35
TP_TIP#2 [mil]
  round 65 hole 46 mask+5: TP(0,0)
  silkscreen extent -40,-40 40,40
TP_TIP#3 [mil]
  round 75 / inner round 75 / far side round 56 hole 46 mask+5: TP(0,0)
  silkscreen extent -40,-40 40,40
TP_TIP#4 [mil]
  round 75 hole 46 mask+5: TP(0,0)
  silkscreen extent -40,-40 40,40
TP_TIP#5 [mil]
  round 56 hole 32 mask+3: TP(0,0)
  silkscreen extent -35,-35 35,35
TP_TIP#6 [mil]
  round 75 hole 46 mask+3: TP(0,0)
  silkscreen extent -40,-40 40,40
TSW-4X2M [mil]
  oval 62x75 hole 38: 1(0,0)
  rect 62x62 hole 38: 2(0,-100) 3(-100,0) 4(-100,-100) 5(-200,0) 6(-200,-100) 7(-300,0) 8(-300,-100)
  silkscreen extent -350,-225 50,-155
TSW-6X2M [mil]
  oval 62x75 hole 38: 1(0,0)
  rect 62x62 hole 38: 2(0,-100) 3(-100,0) 4(-100,-100) 5(-200,0) 6(-200,-100) 7(-300,0) 8(-300,-100) 9(-400,0) 10(-400,-100) 11(-500,0) 12(-500,-100)
  silkscreen extent -550,-225 50,-155
ZEROHM [mil]
  rect 60x60 smd: 1(0,0) 2(135,0)
  silkscreen extent -50,-50 185,50

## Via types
v1: diameter 0.7, hole 0.3, TopLayer to BottomLayer, 3209 vias
v2: diameter 0.68, hole 0.3, TopLayer to BottomLayer, 1006 vias
v3: diameter 0.762, hole 0.508, TopLayer to BottomLayer, 39 vias
v4: diameter 1, hole 0.508, TopLayer to BottomLayer, 20 vias
v5: diameter 1.27, hole 0.508, TopLayer to BottomLayer, 19 vias
v6: diameter 0.6, hole 0.3, TopLayer to BottomLayer, 19 vias
v7: diameter 1.27, hole 0.711, TopLayer to BottomLayer, 10 vias

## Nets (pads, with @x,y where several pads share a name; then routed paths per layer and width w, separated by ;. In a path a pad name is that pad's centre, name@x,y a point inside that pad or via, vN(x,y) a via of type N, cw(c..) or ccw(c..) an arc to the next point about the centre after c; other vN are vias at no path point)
+12: C31.1 K2.1 L1.1 R54.2 R207.1 TP8.TP VR1.4 | length 198.2
  TopLayer w0.406: TP8.TP@106.175,78.61 107.315,77.47 v5(107.315,74.295) ; v5(111.76,48.895) R54.2@115.57,48.895 119.38,48.895 K2.1@119.38,46.355
  TopLayer w0.61: VR1.4@105.842,86.36 105.83,84.575 105.83,78.74 105.83,78.618 TP8.TP@106.007,78.441
  TopLayer w0.762: v5(55.245,75.565) 59.055,79.375 v5(73.025,79.375) ; R207.1@60.325,41.91 v5(60.325,43.8) ; v5(82.55,78.74) 87.63,78.74 88.9,80.01 101.061,80.01 102.331,78.74 TP8.TP@105.83,78.74 ; VR1.4@105.842,86.36 105.842,88.9 111.125,88.9 111.125,98.425 119.38,98.425 120.65,99.695 137.795,99.695 C31.1@137.795,97.155 139.7,95.885 144.78,95.885 L1.1@146.05,97.155
  BottomLayer w0.406: v5(107.315,74.295) 107.315,62.23 111.76,62.23 v5(111.76,48.895)
  BottomLayer w0.762: v5(55.245,75.565) 55.245,60.96 60.325,55.88 v5(60.325,43.8) ; v5(73.025,79.375) 81.28,79.375 v5(82.55,78.74)
+15VBUS: JP7.3 JP7.4 L8.2 | length 10.4
  TopLayer w0.762: L8.2@146.939,91.44 149.225,91.44 150.495,90.17 JP7.3@154.305,90.17 JP7.4@156.845,90.17
-15VBUS: JP7.9 JP7.10 L7.2 | length 11.7
  TopLayer w0.762: L7.2@146.695,85.7 148.6,85.7 151.13,82.55 JP7.9@154.305,82.55 JP7.10@156.845,82.55
A-GAIN: C61.1 JP105.1 L10.2 | length 7
  TopLayer w0.406: JP105.1@153.035,26.035 L10.2@156.845,26.035 C61.1@156.845,29.21
ANTPOWER: JP7.11 JP7.12 L105.2 | length 18.1
  TopLayer w0.762: L105.2@147.2,80 v7(148.5,80) JP7.12@157,80
  BottomLayer w0.762: v7(148.5,80) 148.51,80.01 JP7.11@154.305,80.01 JP7.12@156.845,80.01
ATTEN: C10.1 JP104.1 L107.2 | length 74
  TopLayer w0.406: C10.1@81.915,3.175 86.36,3.175 88.265,1.905 149.225,1.905 L107.2@149.225,3.175
  TopLayer w0.508: C10.1@81.915,3.175 JP104.1@81.915,8.255
BP2: 
BP3: 
BP4: 
BT1: JP101.2 JP103.2 L105.1 R115.2 R116.2 | length 110.2
  TopLayer w0.635: R116.2@59.055,99.06 JP103.2@59.055,93.345 66.04,93.345 ; JP101.2@66.04,92.075 66.04,93.345 ; R115.2@66.04,95.885 66.04,93.345 ; v7(140.5,80.01) 140.51,80 142.23,80 L105.1@142.24,80.01
  BottomLayer w0.635: JP101.2@66.04,92.075 71.12,92.075 71.12,85.09 90.805,85.09 90.805,80.01 100.33,80.01 104.14,76.2 139.065,76.2 139.065,80.01 v7(140.5,80.01)
BT2: R119.2 R120.1 | length 4.4
  TopLayer w0.635: R119.2@45.085,89.535 R120.1@45.085,93.98
BT3: R118.2 R119.1 | length 3.8
  TopLayer w0.635: R119.1@52.07,89.535 R118.2@55.88,89.535
BT4: JP101.1 L101.1 R118.1 | length 30.1
  TopLayer w0.635: L101.1@39.37,89.444 42.431,86.995 62.865,86.995 62.865,89.535 JP101.1@66.04,89.535
BT5: L101.2 L102.1 | length 7.8
  TopLayer w0.635: L102.1@33.655,89.535 39.37,93.345 L101.2@39.37,94.234
BT6: JP102.1 L102.2 | length 5.7
  TopLayer w0.635: JP102.1@28.53,92.7 32.375,92.7 L102.2@33.655,93.98
BT7: LED101.1 R115.1 | length 3.2
  TopLayer w0.406: R115.1@62.865,95.885 LED101.1@62.865,99.06
FBI2: K2.7 R27.2 R80.2 | length 16.5
  TopLayer w0.406: R80.2@121.285,58.42 R80.2@121.666,58.42 122.58,58.42 K2.7@122.58,53.355 122.58,51.435 R27.2@130.81,51.435
FBI3: K2.5 R28.2 | length 7.6
  TopLayer w0.406: K2.5@126.98,53.355 127,57.15 R28.2@130.81,57.15
FBQ2: K2.2 R81.2 RQ27.2 | length 13.9
  TopLayer w0.406: R81.2@122.58,42.545 K2.2@122.58,46.355 122.58,48.26 RQ27.2@130.81,48.26
FBQ3: K2.4 RQ28.2 | length 7
  TopLayer w0.406: K2.4@126.98,46.355 127,43.18 RQ28.2@130.81,43.18
GB1: R13.2 R14.1 | length 5.1
  TopLayer w0.61: R13.2@101.6,17.78 R14.1@106.68,17.78
GB2: L3.2 R14.2 R91.2 | length 19
  TopLayer w0.61: R91.2@101.6,13.335 R91.2@101.854,13.335 107.95,13.335 112.395,17.78 R14.2@113.665,17.78 L3.2@118.491,17.78 L3.2@118.745,17.78
GB3: L4.2 R5.2 R92.1 | length 11.8
  TopLayer w0.635: R92.1@73.025,67.945 73.025,68.338 77.126,71.755 R5.2@79.375,71.755 L4.2@82.931,71.755 L4.2@83.185,71.755
GB4: R5.1 R6.2 | length 3.8
  TopLayer w0.635: R6.2@68.58,71.755 R5.1@72.39,71.755
GB5: RQ5.2 RQ6.2 | length 4.4
  TopLayer w0.762: RQ6.2@67.945,48.26 RQ5.2@72.39,48.26
GB6: LQ4.2 R93.2 RQ5.1 | length 12.8
  TopLayer w0.762: R93.2@71.755,44.45 72.85,44.45 76.66,48.26 RQ5.1@79.375,48.26 LQ4.2@82.931,48.26
GB7: RQ13.2 RQ14.1 | length 5.1
  TopLayer w0.61: RQ13.2@101.6,5.715 RQ14.1@106.68,5.715
GB8: LQ3.2 R94.2 RQ14.2 | length 18.5
  TopLayer w0.61: R94.2@101.6,9.525 102.235,8.89 109.22,8.89 112.395,5.715 RQ14.2@113.665,5.715 LQ3.2@118.491,5.715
